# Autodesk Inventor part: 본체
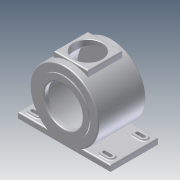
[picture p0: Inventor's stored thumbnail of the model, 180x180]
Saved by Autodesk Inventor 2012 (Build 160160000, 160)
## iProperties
Created: 2015-06
Part Number: 본체
Material: Default
Document SubType Name: Modeling
Designer: User
Density: 1 g/cm^3
Author: User
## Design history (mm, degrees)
sketch "스케치4"
  geometry: L1 (-67, 0)-(67, 0); L2 (-67, 0)-(-67, 65); L3 (-67, 65)-(-54, 65); L4 (-54, 65)-(-54, 85); L5 (-54, 85)-(64, 85); L6 (64, 85)-(64, 65); L7 (64, 65)-(67, 65); L8 (67, 65)-(67, 47.5); L9 (67, 47.5)-(56, 47.5); L10 (56, 47.5)-(56, 77); L11 (56, 77)-(-46, 77); L12 (-46, 77)-(-46, 31); L13 (-46, 31)-(-42.5, 29.368); L14 (-42.5, 29.368)-(-42.5, 23.5); L15 (-42.5, 23.5)-(-56.5, 23.5); L16 (-56.5, 23.5)-(-56.5, 15); L17 (-56.5, 15)-(-59.5, 15); L18 (-59.5, 15)-(-59.5, 0); 3 further points
  constraints: 36 end point, 11 parallel, 5 perpendicular, 2 midpoint, 2 vertical alignment, 1 coincident, 1 horizontal, 1 point on line
  dimensions: "d9" = 134 distance of L1.start L1.end; "d11" = 30 diameter of L17 L1; "d12" = 3 distance of L16.end L17.end; "d13" = 14 distance of L14.end L15.end; "d14" = 47 diameter of L15 L1; "d15" = 115 deg angle of L12 L13; "d16" = 3.5 distance between parallel lines of L14 L12; "d17" = 62 diameter of L12.end L1; "d18" = 130 diameter of L3 L1; "d19" = 13 distance of L2.end L3.end; "d21" = 118 distance of L4.end L5.end; "d22" = 170 diameter of L5 L1; "d23" = 95 diameter of L9 L1; "d24" = 130 diameter of L7.end L1; "d25" = 154 diameter of L11 L1; "d26" = 102 distance of L10.end L11.end; "d27" = 7.5 distance between parallel lines of L2 L18
revolve "회전1" sketch "스케치4" stored, may be unused: angle "d28" = 90 deg
node "작업 평면1"
sketch "스케치5"
  geometry: L1 (-64, 115)-(54, 115); L2 (54, 115)-(54, -115); L3 (54, -115)-(-64, -115); L4 (-64, -115)-(-64, 115); L5 (-64, 85)-(-64, -85) reference; L6 (54, 85)-(54, -85) reference; 3 further points
  constraints: 8 end point, 3 midpoint, 2 parallel, 1 horizontal, 1 horizontal alignment, 1 perpendicular
  dimensions: "d30" = 118 distance of L1.start L1.end; "d31" = 230 distance of L3.end L1.start
extrude "돌출4" join sketch "스케치5" distance "d32" = 8; taper "d33" = 0 deg
extrude "돌출5" join sketch "스케치5" distance "d34" = 6; taper "d35" = 0 deg
sketch "스케치6"
  geometry: L1 (56, 71)-(-46, 71) reference; L2 (-46, 71)-(-46, 71) reference; L3 (-46, 71)-(56, 71) reference; L4 (56, 71)-(56, 71) reference; L5 (56, -77)-(-46, -77) reference; L6 (56, -77)-(56, 71) reference; L7 (-46, -77)-(-46, 71) reference; L8 (-59, 0)-(59, 0); L9 (-46, -77)-(56, -77); L10 (56, -69)-(-46, -69); L11 (-46, -77)-(-46, -69); 2 further points
  constraints: 8 end point, 3 perpendicular, 2 point on line, 1 coincident, 1 collinear, 1 midpoint
  dimensions: "d36" = 118 distance of L8.start L8.end; "d37" = 8 distance of L5.end L10.end
revolve "회전2" sketch "스케치6" stored, may be unused: angle "d38" = 90 deg
node "작업 평면2"
sketch "스케치7"
  geometry: L1 (64, 115)-(-54, 115) reference; L2 (-54, 115)-(-54, 46.733) reference; L3 (64, 46.733)-(64, 115) reference; L4 (64, -115)-(64, -46.733) reference; L5 (-54, -115)-(64, -115) reference; L6 (-54, -46.733)-(-54, -115) reference; L7 (-40, -81)-(-40, -97); L8 (-32, -81)-(-32, -97); L9 (-45, -97)-(-45, -81); L10 (-27, -81)-(-27, -97); A1 r 4 centre (-36, -81) between (-32, -81) and (-40, -81); A2 r 4 centre (-36, -97) between (-40, -97) and (-32, -97); A3 r 9 centre (-36, -81) between (-27, -81) and (-45, -81); A4 r 9 centre (-36, -97) between (-45, -97) and (-27, -97); 1 further point
  constraints: 8 end point, 8 point on circle, 4 centre point, 3 tangent, 2 parallel, 1 vertical alignment, 3 other
  dimensions: "d40" = 8 diameter of A1; "d41" = 8 diameter of A2; "d42" = 16 distance of A2.centre A1.centre; "d43" = 18 distance between parallel lines of L10 L9; "d44" = 18 distance from line of L6 A2.centre; "d45" = 18 distance from line of L5 A2.centre
extrude "돌출6" join sketch "스케치7" stored distance "d46" = 6; taper "d47" = 0 deg
extrude "돌출7" cut sketch "스케치7" stored distance "d48" = 6; taper "d49" = 0 deg
fillet "모깎기1" dims "d53" = 0.3
fillet "모깎기2" dims "d54" = 3
fillet "모깎기3" dims "d55" = 3
fillet "모깎기4" dims "d56" = 3
node "작업 평면4"
sketch "스케치9"
  geometry: L1 (-51, -85)-(61, -85) reference; L2 (-51, 85)-(61, 85) reference; L3 (5, -85)-(5, 85); L4 (-37.5, -42.5)-(47.5, -42.5); L5 (47.5, -42.5)-(47.5, 42.5); L6 (47.5, 42.5)-(-37.5, 42.5); L7 (-37.5, 42.5)-(-37.5, -42.5); C1 r 35 at (5, 0); 3 further points
  constraints: 10 end point, 5 midpoint, 2 parallel, 1 centre point, 1 horizontal, 1 horizontal alignment, 1 perpendicular, 1 vertical alignment
  dimensions: "d62" = 70 diameter of C1; "d63" = 85 distance of L4.start L4.end; "d64" = 85 distance of L4.end L5.end; "d65" = 85 distance from line of L1 C1.centre (derived)
extrude "돌출8" join sketch "스케치9" stored distance "d66" = 6; taper "d67" = 0 deg
extrude "돌출9" cut sketch "스케치9" stored distance "d68" = 6; taper "d69" = 0 deg
fillet "모깎기5" dims "d70" = 3
fillet "모깎기6" dims "d71" = 3
chamfer "모따기1" distance "d72" = 1; stored, may be unused: second distance "d73" = 2, angle "d74" = 45 deg
node "솔리드2"
pattern_linear "직사각형 패턴1" dims "d52" = 82
mirror "대칭1"
node "투영된 루프1"
other parameters: "d29" = 77, "d39" = -17, "d61" = -173
